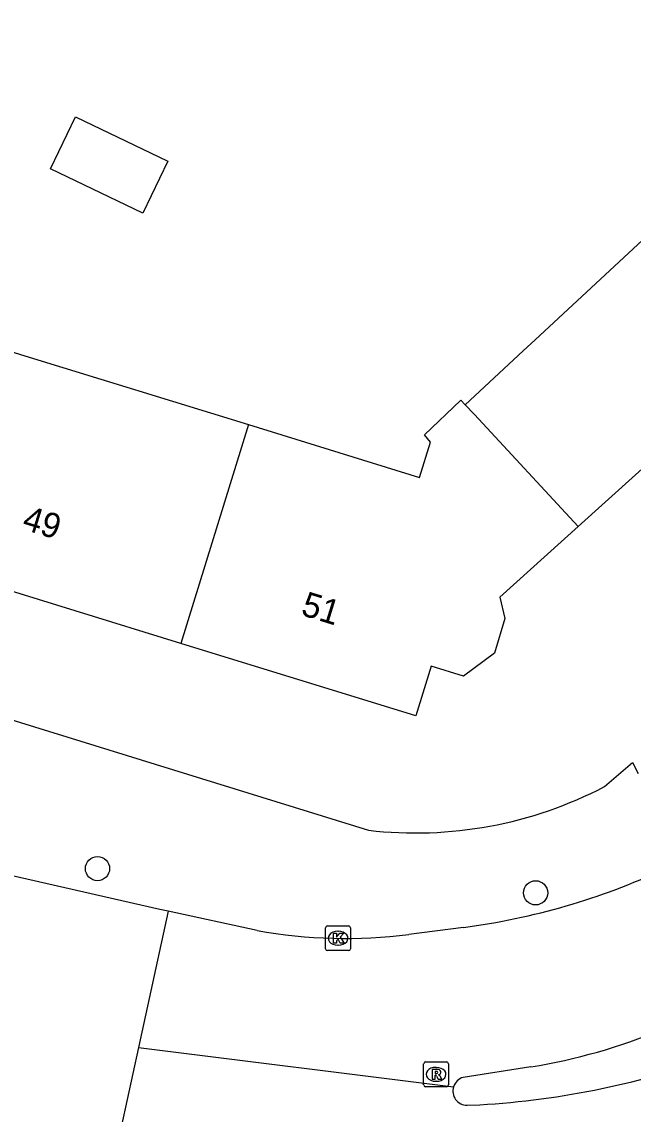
# Model space of a CAD drawing. Extents: x 160356 to 161355, y 381727 to 382845.
# Drawn here: x 161223.53 to 161248.22, y 382200.39 to 382244.5 of the extents above; entities that cross this region are included whole.
import ezdxf

# ---------------------------------------------------------------- set-up
doc = ezdxf.new("R2010")
doc.units = 0
for name, color, linetype in [('IMGEO_Boom', 7, 'Continuous'), ('IMGEO_Kolk', 7, 'Continuous'), ('IMGEO_Pand', 7, 'Continuous'), ('IMGEO_Pand_nummerreeks', 7, 'Continuous'), ('IMGEO_Rijbaan_lokaal_gesloten', 7, 'Continuous'), ('IMGEO_Rijbaan_lokaal_open', 7, 'Continuous'), ('IMGEO_Rioolput', 7, 'Continuous'), ('IMGEO_Voetpad_open', 7, 'Continuous')]:
    doc.layers.add(name, color=color, linetype=linetype)

msp = doc.modelspace()

# ---------------------------------------------------------------- linework, layer by layer
at = {"layer": 'IMGEO_Boom'}
for centre in [(161226.588, 382210.308), (161244.279, 382209.328)]:
    msp.add_circle(centre, 0.489, dxfattribs=at)
at = {"layer": 'IMGEO_Kolk'}
for p, q in [((161235.801, 382207.068), (161235.801, 382207.92)), ((161235.876, 382207.994), (161236.728, 382207.994)), ((161236.802, 382207.92), (161236.802, 382207.068)), ((161236.289, 382207.774), (161236.314, 382207.774)), ((161236.312, 382207.214), (161236.287, 382207.214)), ((161236.728, 382206.994), (161235.876, 382206.994))]:
    msp.add_line(p, q, dxfattribs=at)
for points in [[(161235.801, 382207.068), (161235.801, 382207.92)], [(161235.876, 382207.994), (161236.728, 382207.994)], [(161236.802, 382207.92), (161236.802, 382207.068)], [(161236.122, 382207.694), (161236.245, 382207.694), (161236.245, 382207.543), (161236.375, 382207.694), (161236.539, 382207.694), (161236.393, 382207.543), (161236.546, 382207.294), (161236.394, 382207.294), (161236.309, 382207.458), (161236.245, 382207.391), (161236.245, 382207.294), (161236.122, 382207.294), (161236.122, 382207.694)], [(161236.728, 382206.994), (161235.876, 382206.994)]]:
    msp.add_lwpolyline(points, dxfattribs=at)
for centre, start, end in [((161235.878, 382207.918), 91.552, 178.448), ((161235.878, 382207.918), 91.552, 178.448), ((161236.726, 382207.918), 1.552, 88.448), ((161236.726, 382207.918), 1.552, 88.448), ((161235.878, 382207.07), 181.552, 268.448), ((161235.878, 382207.07), 181.552, 268.448), ((161236.726, 382207.07), 271.552, 358.448), ((161236.726, 382207.07), 271.552, 358.448)]:
    msp.add_arc(centre, 0.0765, start, end, dxfattribs=at)
for centre, major_axis, ratio, start_param, end_param in [((161236.288, 382207.494), (-0.387, 0.002), 0.722429, 4.712389, 7.853982), ((161236.313, 382207.494), (-0.39, 0.002), 0.717154, 1.570796, 4.712389)]:
    msp.add_ellipse(centre, major_axis=major_axis, ratio=ratio, start_param=start_param, end_param=end_param, dxfattribs=at)
at = {"layer": 'IMGEO_Pand'}
for points in [[(161225.693, 382240.664), (161229.422, 382238.88), (161228.751, 382237.476), (161228.416, 382236.775), (161224.685, 382238.559), (161225.021, 382239.26), (161225.693, 382240.664)], [(161241.439, 382229.035), (161243.783, 382231.212), (161244.268, 382231.662), (161251.613, 382238.484), (161252.992, 382237.029)], [(161219.863, 382232.191), (161221.355, 382231.731), (161223.651, 382231.018), (161232.68, 382228.236)], [(161259.162, 382230.519), (161253.689, 382225.333), (161250.77, 382228.413), (161246.005, 382224.12)], [(161232.68, 382228.236), (161239.592, 382226.107), (161240.038, 382227.529), (161239.79, 382227.822), (161241.266, 382229.221), (161241.439, 382229.035)], [(161241.439, 382229.035), (161241.807, 382228.639), (161246.005, 382224.12)], [(161232.68, 382228.236), (161229.959, 382219.402)], [(161246.005, 382224.12), (161242.835, 382221.263), (161243.041, 382220.405), (161242.624, 382219), (161241.368, 382218.078), (161240.063, 382218.48), (161239.446, 382216.479), (161229.959, 382219.402)], [(161229.959, 382219.402), (161217.14, 382223.352)]]:
    msp.add_lwpolyline(points, dxfattribs=at)
at = {"layer": 'IMGEO_Rijbaan_lokaal_gesloten'}
for points in [[(161229.435, 382208.582), (161228.242, 382203.088)], [(161233.035, 382207.802), (161229.435, 382208.582)], [(161241.373, 382207.931), (161239.159, 382207.651)], [(161228.242, 382203.088), (161226.872, 382196.778)], [(161228.242, 382203.088), (161240.967, 382201.499)], [(161244.091, 382202.3), (161241.358, 382201.875)], [(161241.521, 382200.752), (161242.029, 382200.77)]]:
    msp.add_lwpolyline(points, dxfattribs=at)
for centre, radius, start, end in [((161237.686, 382235.723), 28.035, 277.5569, 294.8438), ((161236.595, 382227.904), 20.415, 259.9586, 277.2165), ((161240.25, 382225.81), 23.822, 279.2792, 292.5026), ((161239.957, 382235.248), 34.54, 273.4388, 289.9426), ((161241.508, 382201.327), 0.568, 105.3473, 162.412), ((161241.51, 382201.323), 0.571, 162.0634, 271.0603)]:
    msp.add_arc(centre, radius, start, end, dxfattribs=at)
at = {"layer": 'IMGEO_Rijbaan_lokaal_open'}
msp.add_lwpolyline([(161229.435, 382208.582), (161229.11, 382208.652), (161214.044, 382212.09), (161210.203, 382212.962)], dxfattribs=at)
at = {"layer": 'IMGEO_Rioolput'}
for p, q in [((161239.759, 382201.572), (161239.759, 382202.424)), ((161239.834, 382202.498), (161240.686, 382202.498)), ((161240.247, 382202.278), (161240.272, 382202.278)), ((161240.76, 382202.424), (161240.76, 382201.572)), ((161240.27, 382201.718), (161240.245, 382201.718)), ((161240.686, 382201.498), (161239.834, 382201.498))]:
    msp.add_line(p, q, dxfattribs=at)
for points in [[(161239.759, 382201.572), (161239.759, 382202.424)], [(161239.834, 382202.498), (161240.686, 382202.498)], [(161240.348, 382202.196), (161240.096, 382202.198), (161240.096, 382201.798)], [(161240.76, 382202.424), (161240.76, 382201.572)], [(161240.096, 382201.798), (161240.22, 382201.798), (161240.22, 382201.96), (161240.231, 382201.96)], [(161240.274, 382202.117), (161240.22, 382202.117), (161240.22, 382202.036)], [(161240.22, 382202.036), (161240.272, 382202.036)], [(161240.278, 382201.931), (161240.349, 382201.798), (161240.489, 382201.798), (161240.424, 382201.924)], [(161240.686, 382201.498), (161239.834, 382201.498)]]:
    msp.add_lwpolyline(points, dxfattribs=at)
for centre, radius, start, end in [((161239.836, 382202.422), 0.0765, 91.552, 178.448), ((161239.836, 382202.422), 0.0765, 91.552, 178.448), ((161240.347, 382202.086), 0.109, 350.3612, 89.416), ((161240.684, 382202.422), 0.0765, 1.552, 88.448), ((161240.684, 382202.422), 0.0765, 1.552, 88.448), ((161240.23, 382201.907), 0.0533, 26.0293, 88.6989), ((161240.256, 382202.225), 0.19, 274.7715, 282.9687), ((161240.28, 382202.021), 0.0964, 77.0061, 93.1865), ((161240.294, 382202.078), 0.0378, 276.6634, 79.6772), ((161240.345, 382202.086), 0.112, 277.5842, 350.9817), ((161240.329, 382201.871), 0.108, 29.5134, 73.7905), ((161239.836, 382201.574), 0.0765, 181.552, 268.448), ((161239.836, 382201.574), 0.0765, 181.552, 268.448), ((161240.684, 382201.574), 0.0765, 271.552, 358.448), ((161240.684, 382201.574), 0.0765, 271.552, 358.448)]:
    msp.add_arc(centre, radius, start, end, dxfattribs=at)
for centre, major_axis, ratio, start_param, end_param in [((161240.246, 382201.998), (-0.387, 0.002), 0.722429, 4.712389, 7.853982), ((161240.271, 382201.998), (-0.39, 0.002), 0.717154, 1.570796, 4.712389)]:
    msp.add_ellipse(centre, major_axis=major_axis, ratio=ratio, start_param=start_param, end_param=end_param, dxfattribs=at)
at = {"layer": 'IMGEO_Voetpad_open'}
for points in [[(161131.647, 382244.501), (161134.098, 382243.849), (161237.527, 382211.856)], [(161247.067, 382213.621), (161248.192, 382214.595), (161248.421, 382214.153)]]:
    msp.add_lwpolyline(points, dxfattribs=at)
msp.add_arc((161239.426, 382228.256), 16.51, 263.3949, 297.5687, dxfattribs=at)

# ---------------------------------------------------------------- texts
at = {"layer": 'IMGEO_Pand_nummerreeks'}
for s, p in [('49', (161223.501, 382224.029)), ('51', (161234.763, 382220.56))]:
    msp.add_text(s, height=1, rotation=342.8743, dxfattribs=at).set_placement(p)

doc.saveas('drawing.dxf')
